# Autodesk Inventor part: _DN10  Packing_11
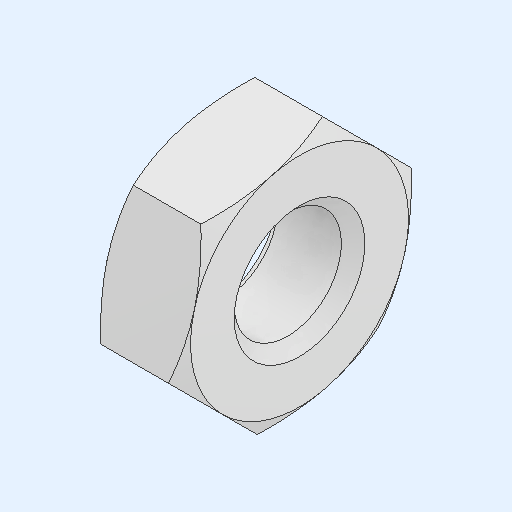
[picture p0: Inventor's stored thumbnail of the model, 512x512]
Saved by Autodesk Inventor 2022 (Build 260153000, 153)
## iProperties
Created: 2021-12
Part Number: _DN10  Packing_11
Material: Generico
Document SubType Name: Modeling
Designer: admin
Density: 1 g/cm^3
Appearance: Default
Author: admin
Revision Number: NONE
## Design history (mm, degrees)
feature "_DN10  Packing"
node "Solido1"
